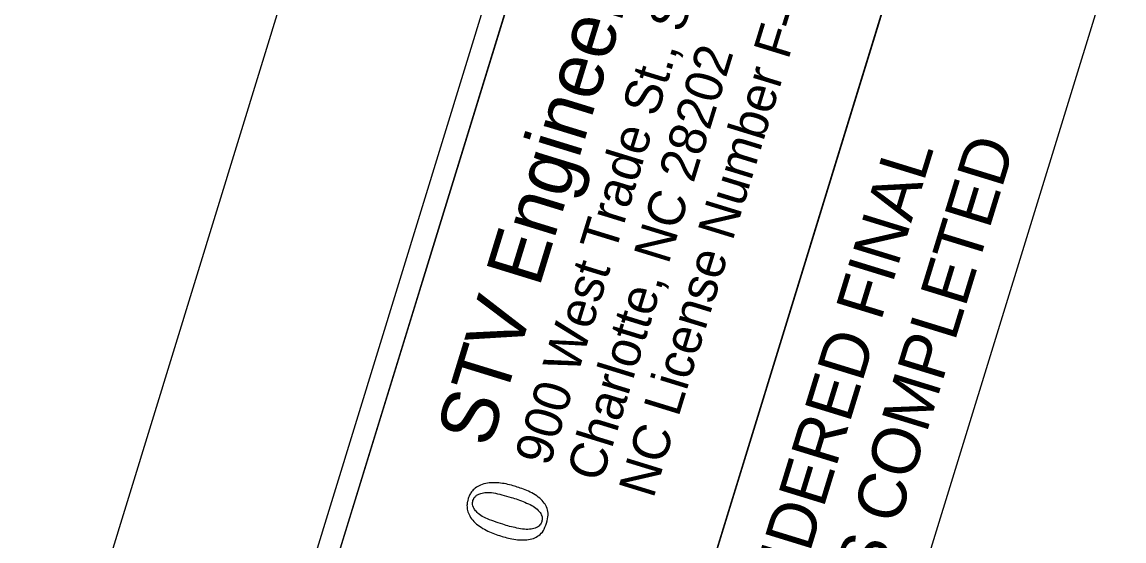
# Model space of a CAD drawing. Extents: x 1439200 to 1642353, y 394562 to 606444.
# Drawn here: x 1641889.6 to 1641940.2, y 395207.7 to 395231.5 of the extents above; entities that cross this region are included whole.
import ezdxf

# ---------------------------------------------------------------- set-up
doc = ezdxf.new("R2010")
doc.units = 0
for name, color, linetype in [('North Arrow NAD83 CELL', 7, 'Continuous'), ('Old_Level_60', 7, 'Continuous'), ('Sheet Plot Border Inside CELL', 7, 'Continuous'), ('Sheet Plot Border Outside CELL', 7, 'Continuous'), ('Sheet Sticker Exception Certification CELL', 7, 'Continuous'), ('UC Plan Sheet 34 CELL', 7, 'Continuous')]:
    doc.layers.add(name, color=color, linetype=linetype)

msp = doc.modelspace()

# ---------------------------------------------------------------- linework, layer by layer
at = {"layer": 'North Arrow NAD83 CELL'}
msp.add_line((1641939.44, 395233.693), (1641927.806, 395195.866), dxfattribs=at)
at = {"layer": 'Old_Level_60'}
for p, q in [((1641913.446, 395208.588), (1641913.445, 395208.586)), ((1641913.664, 395208.52), (1641913.664, 395208.52))]:
    msp.add_line(p, q, dxfattribs=at)
msp.add_lwpolyline([(1641893.468, 395172.511), (1641916.99, 395248.99), (1641932.814, 395244.123), (1641909.291, 395167.644)], close=True, dxfattribs=at)
for points in [[(1641912.198, 395210.216), (1641912.108, 395210.241), (1641911.886, 395210.303), (1641911.562, 395210.361), (1641911.202, 395210.376), (1641910.866, 395210.354), (1641910.551, 395210.242), (1641910.326, 395210.085), (1641910.179, 395209.907), (1641910.102, 395209.756), (1641910.069, 395209.659), (1641910.059, 395209.629)], [(1641913.664, 395208.52), (1641913.705, 395208.668), (1641913.768, 395208.892), (1641913.706, 395209.202), (1641913.575, 395209.442), (1641913.365, 395209.67), (1641913.076, 395209.859), (1641912.763, 395210.029), (1641912.458, 395210.127), (1641912.27, 395210.192), (1641912.198, 395210.216)], [(1641910.059, 395209.629), (1641910.051, 395209.599), (1641910.024, 395209.5), (1641910.002, 395209.331), (1641910.024, 395209.101), (1641910.121, 395208.845), (1641910.319, 395208.576), (1641910.585, 395208.368), (1641910.89, 395208.179), (1641911.192, 395208.045), (1641911.41, 395207.971), (1641911.498, 395207.941)], [(1641910.283, 395209.56), (1641910.296, 395209.594), (1641910.318, 395209.652), (1641910.371, 395209.728), (1641910.476, 395209.816), (1641910.637, 395209.889), (1641910.88, 395209.934), (1641911.219, 395209.921), (1641911.612, 395209.815), (1641911.895, 395209.737), (1641912.039, 395209.697)], [(1641912.039, 395209.697), (1641912.137, 395209.669), (1641912.351, 395209.607), (1641912.667, 395209.474), (1641912.996, 395209.337), (1641913.249, 395209.153), (1641913.415, 395208.952), (1641913.484, 395208.758), (1641913.457, 395208.639), (1641913.446, 395208.588)], [(1641911.658, 395208.46), (1641911.517, 395208.507), (1641911.239, 395208.602), (1641910.854, 395208.735), (1641910.566, 395208.915), (1641910.391, 395209.089), (1641910.299, 395209.239), (1641910.261, 395209.372), (1641910.261, 395209.464), (1641910.275, 395209.525), (1641910.283, 395209.56)], [(1641913.445, 395208.586), (1641913.426, 395208.538), (1641913.381, 395208.425), (1641913.215, 395208.303), (1641912.965, 395208.23), (1641912.652, 395208.22), (1641912.303, 395208.292), (1641911.967, 395208.358), (1641911.755, 395208.428), (1641911.658, 395208.46)], [(1641911.498, 395207.941), (1641911.572, 395207.921), (1641911.764, 395207.869), (1641912.07, 395207.778), (1641912.425, 395207.743), (1641912.771, 395207.737), (1641913.072, 395207.807), (1641913.315, 395207.933), (1641913.541, 395208.154), (1641913.615, 395208.374), (1641913.664, 395208.52)]]:
    msp.add_open_spline(points, degree=3, dxfattribs=at)
at = {"layer": 'Sheet Plot Border Inside CELL'}
msp.add_lwpolyline([(1641940.985, 395330.472), (1641745.02, 394693.328), (1642148.411, 394569.258), (1642344.376, 395206.402)], close=True, dxfattribs=at)
at = {"layer": 'Sheet Plot Border Outside CELL'}
msp.add_lwpolyline([(1641932.931, 395334.833), (1641734.908, 394690.997), (1642155.465, 394561.647), (1642353.488, 395205.483)], close=True, dxfattribs=at)
at = {"layer": 'Sheet Sticker Exception Certification CELL'}
for p, q in [((1641909.291, 395167.644), (1641932.814, 395244.123)), ((1641941.798, 395241.36), (1641918.276, 395164.88))]:
    msp.add_line(p, q, dxfattribs=at)
at = {"layer": 'UC Plan Sheet 34 CELL'}
msp.add_lwpolyline([(1641940.49, 395325.393), (1641764.104, 394751.906), (1642165.545, 394628.435), (1642341.931, 395201.923)], close=True, dxfattribs=at)

# ---------------------------------------------------------------- texts
at = {"layer": 'Old_Level_60'}
for s, height, p in [('STV Engineers, Inc.', 2.6, (1641911.055, 395211.918)), ('900 West Trade St., Suite 715', 1.7, (1641913.795, 395211.076)), ('NC License Number F-0991', 1.7, (1641918.574, 395209.606)), ('Charlotte, NC 28202', 1.7, (1641916.184, 395210.341))]:
    msp.add_text(s, height=height, rotation=72.9038, dxfattribs=at).set_placement(p)
at = {"layer": 'Sheet Sticker Exception Certification CELL'}
for s, p in [('UNLESS ALL SIGNATURES COMPLETED', (1641918.492, 395171.51)), ('DOCUMENT NOT CONSIDERED FINAL', (1641915.724, 395174.483))]:
    msp.add_text(s, height=2.2, rotation=72.9038, dxfattribs=at).set_placement(p)

doc.saveas('drawing.dxf')
